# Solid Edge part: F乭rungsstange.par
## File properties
Username: bmolnar
Dokumentum tartalom típus: 0
Author: bmolnar
Last saved by: bmolnar
Revision: 80
Sűrűség: 0,000 kg/m^3
Pontosság: 0,990
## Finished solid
Body 1: solid body, 8 faces, 7 edges, 1 vertex.
  Faces by surface: cone 4, cylinder 2, plane 2
  Edges by curve: circle 7
Bounding box of the edges (mm): 55.000 x 14.000 x 14.000, from (0, -7, -7) to (55, 7, 7).
Cylindrical faces by radius (mm): R3.3235 x1, R7 x1
Conical faces (half-angle, radius in mm at the cone's reference point): 45 deg R3.6235 x1, 45 deg R6.9 x1, 45 deg R7 x1, 59 deg R1.6618 x1
Planar faces by outward normal: +x 1, -x 1
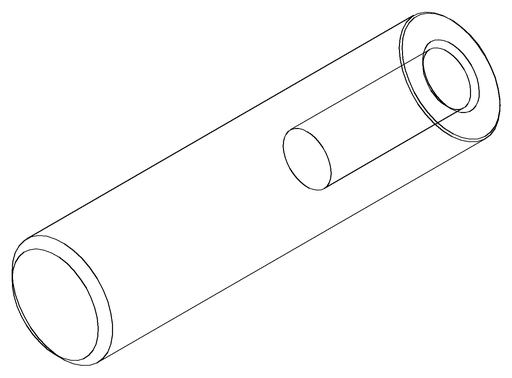
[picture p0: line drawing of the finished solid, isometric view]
